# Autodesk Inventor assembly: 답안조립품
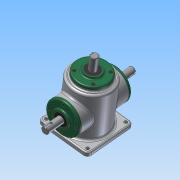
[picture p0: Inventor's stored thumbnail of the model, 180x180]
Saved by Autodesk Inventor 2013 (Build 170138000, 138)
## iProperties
Created: 2015-10
Part Number: 답안조립품
Document SubType Name: Assembly
Designer: Administrator
Author: Administrator
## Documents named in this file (14)
- C:\Users\Administrator\Desktop\451008V1018\답안조립품.iam
- C:\Users\Administrator\Desktop\451008V1018\본체.ipt
- C:\Users\Administrator\Desktop\451008V1018\M4.ipt
- C:\Users\Administrator\Desktop\451008V1018\메인 베벨기어.ipt
- C:\Users\Administrator\Desktop\451008V1018\메인 축.ipt
- 메인 축.ipt
- C:\Users\Administrator\Desktop\451008V1018\베어링 6203.ipt
- C:\Users\Administrator\Desktop\451008V1018\서브 베벨기어.ipt
- C:\Users\Administrator\Desktop\451008V1018\서브 축.ipt
- 서브 축.ipt
- C:\Users\Administrator\Desktop\451008V1018\오일실.ipt
- C:\Users\Administrator\Desktop\451008V1018\커버.ipt
- C:\Users\Administrator\Desktop\451008V1018\키 4x4.ipt
- C:\Users\Administrator\Desktop\451008V1018\키 5x5.ipt
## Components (12 placed, 1 different names)
1. M4:3
2. M4:4
3. M4:5
4. M4:6
5. M4:1
6. M4:7
7. M4:8
8. M4:9
9. M4:2
10. M4:10
11. M4:11
12. M4:12
